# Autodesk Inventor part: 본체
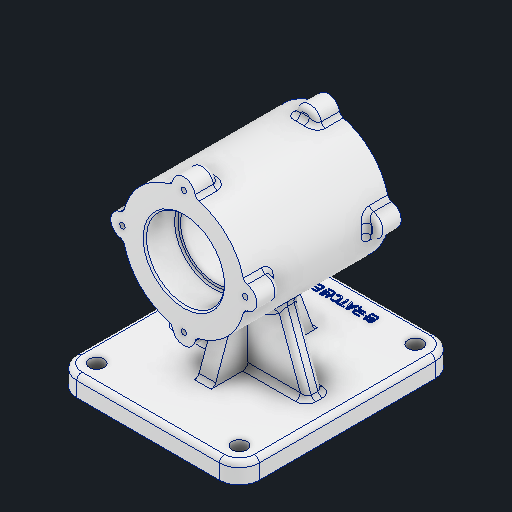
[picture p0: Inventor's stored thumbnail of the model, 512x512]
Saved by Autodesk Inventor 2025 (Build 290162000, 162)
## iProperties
Created: 2025-08
Part Number: 본체
Material: 알루미늄 6061
Document SubType Name: Modeling
Designer: infra08
Density: 2.7 g/cm^3
Appearance: 알루미늄 - 평지
Mass: 1223.04 g
Surface Area: 803.281 cm^2
Volume: 452.979 cm^3
Author: infra08
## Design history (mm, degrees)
sketch "스케치1"
  geometry: L1 (55, 65)-(-55, 65); L2 (-55, 65)-(-55, -65); L3 (-55, -65)-(55, -65); L4 (55, -65)-(55, 65); L5 (55, 65)-(-55, -65); L6 (-55, 65)-(55, -65); C1 r 4.5 at (-43, 53); C2 r 4.5 at (-43, -53); C3 r 4.5 at (43, -53); C4 r 4.5 at (43, 53); 2 further points
  constraints: 12 end point, 4 centre point, 2 horizontal alignment, 2 midpoint, 2 parallel, 2 vertical alignment, 1 coincident, 1 horizontal, 1 perpendicular
  dimensions: "d0" = 130 distance of L1.end L2.end; "d1" = 110 distance of L2.end L3.end; "d3" = 9 diameter of C1; "d4" = 9 diameter of C3; "d5" = 9 diameter of C2; "d6" = 12 distance from line of C1.centre L1; "d7" = 12 distance from line of L3 C2.centre (= d6); "d8" = 12 distance from line of L2 C1.centre (= d6); "d9" = 12 distance from line of L4 C3.centre; "d10" = 9 diameter of C4
extrude "돌출1" new body sketch "스케치1" distance "d11" = 12; taper "d12" = 0 deg
sketch "스케치2"
  geometry: L1 (70, 43.5)-(107, 43.5); L2 (107, -43.5)-(70, -43.5); L3 (70, -43.5)-(70, 43.5); L4 (93.5, 43.5)-(93.5, 24.5); L5 (93.5, 24.5)-(91, 24.5); L6 (91, 24.5)-(91, -24.5); L7 (91, -24.5)-(93.5, -24.5); L8 (93.5, -24.5)-(93.5, -43.5); L9 (107, 43.5)-(107, -43.5); L10 (0, 65)-(0, -65) reference; L11 (-12, -65)-(-12, 65) reference; 2 further points
  constraints: 18 end point, 4 perpendicular, 4 point on line, 2 vertical, 1 horizontal, 1 midpoint
  dimensions: "d13" = 87 distance between parallel lines of L2 L1; "d14" = 19 distance of L4.start L4.end; "d15" = 19 distance of L7.end L8.end (= d14); "d16" = 37 distance between parallel lines of L3 L9; "d17" = 23.5 distance between parallel lines of L3 L4; "d18" = 21 distance between parallel lines of L3 L6; "d19" = 43.5 distance from line of point (0, 0) L1 (= 0.5 x d13); "d20" = 82 distance between parallel lines of L11 L3
revolve "회전1" sketch "스케치2" stored, may be unused: angle "d21" = 90 deg
sketch "스케치3"
  geometry: C1 r 7 at (0, 37); 4 further points
  constraints: 1 centre point, 1 vertical alignment, 2 other
  dimensions: "d22" = 14 diameter of C1
extrude "돌출2" join sketch "스케치3" distance "d23" = 14; taper "d24" = 0 deg
sketch "스케치4"
  geometry: A1 r 7 centre (0, 0) between (6.969, -0.662) and (-6.969, -0.662) reference; 1 further point
hole "구멍1" sketch "스케치4" at (0, 0) diameter "d25" = 3.242; stored, may be unused: countersink angle "d29" = 90 deg, drill point angle "d31" = 118 deg; dims "d26" = 8, "d27" = 4, "d28" = 2, "d30" = 10
sketch "스케치5"
  geometry: L1 (0, -30)-(33, -17.989); L2 (0, -65)-(0, -30); L3 (31.379, 43.5)-(34.621, 43.5) reference; L4 (33, -29.5)-(33, 29.5) reference; L5 (33, 0)-(0, 0); L6 (0, 30)-(33, 17.989); 1 further point
  constraints: 8 end point, 2 midpoint, 2 symmetric about line, 2 vertical alignment, 1 horizontal, 1 vertical
  dimensions: "d36" = 110 deg angle of L2 L1; "d37" = 30 distance of L5.end L1.start
sketch "스케치7"
  geometry: L1 (55, 0)-(-55, 0) reference; L2 (-41, 0)-(-25.336, 43.036); L3 (-25.336, 43.036)-(-25.336, 0); L4 (-55, 0)-(55, 0) reference; L5 (0, 26)-(0, 0); A1 r 37 centre (0, 70) between (-36.338, 63.031) and (-6.969, 33.662) reference; A2 r 7 centre (0, 33) between (-6.969, 33.662) and (6.969, 33.662) reference
  constraints: 6 end point, 2 point on circle, 2 point on line, 1 perpendicular, 1 vertical
  dimensions: "d47" = 14 distance of L1.end L2.start; "d48" = 110 deg angle of L1 L2
sketch "스케치6"
  geometry: L1 (-5, 17.989)-(5, 17.989); L2 (5, 17.989)-(5, -17.989); L3 (5, -17.989)-(-5, -17.989); L4 (-5, -17.989)-(-5, 17.989); L5 (-5, 17.989)-(5, -17.989); L6 (5, 17.989)-(-5, -17.989); L7 (-25.336, 5)-(25.336, 5); L8 (25.336, 5)-(25.336, -5); L9 (25.336, -5)-(-25.336, -5); L10 (-25.336, -5)-(-25.336, 5); L11 (-25.336, 5)-(25.336, -5); L12 (25.336, 5)-(-25.336, -5); L13 (0, 30)-(0, 17.989) reference; L14 (-41, 0)-(-25.336, 0) reference; L15 (-25.336, 0)-(25.336, 0); L16 (25.336, 0)-(25.336, -10); L17 (25.336, -10)-(-25.336, -10); L18 (-25.336, -10)-(-25.336, 0); L19 (-25.336, 0)-(25.336, -10); L20 (25.336, 0)-(-25.336, -10); L21 (-55, 65)-(55, 65) reference; L22 (5, 11.484)-(-5, 11.484); L23 (-5, 11.484)-(-5, -21.484); L24 (-5, -21.484)-(5, -21.484); L25 (5, -21.484)-(5, 11.484); L26 (5, 11.484)-(-5, -21.484); L27 (-5, 11.484)-(5, -21.484); 16 further points
  constraints: 48 end point, 13 midpoint, 8 parallel, 4 coincident, 4 horizontal, 4 perpendicular, 2 vertical alignment
  dimensions: "d38" = 10 distance between parallel lines of L4 L2; "d49" = 10 distance between parallel lines of L7 L9; "d66" = 70 distance from line of point (0, -5) L21; "d67" = 10 distance of L17.end L15.start; "d79" = 10 distance of L23.end L24.end
extrude "돌출3" join sketch "스케치6" stored distance "d39" = 14; taper "d40" = 0 deg
feature "리브1" dims "d41" = 1, "d42" = 10, "d43" = 0, "d44" = 0, "d45" = 1, "d46" = 1
feature "리브3" dims "d56" = 1, "d57" = 10, "d58" = 0, "d59" = 0, "d60" = 1, "d61" = 1
feature "리브4" dims "d68" = 1, "d69" = 10, "d70" = 0, "d71" = 0, "d72" = 1, "d73" = 1
fillet "모깎기1" dims "d62" = 12
fillet "모깎기3" dims "d64" = 3
sketch "스케치8" dims "d0" = 130, "d1" = 110, "d3" = 9, "d4" = 9, "d5" = 9, "d6" = 12, "d7" = 12 (= d6), "d8" = 12 (= d6), "d9" = 12, "d10" = 9
  geometry: L1 (21.187, 50.113)-(-21.187, 50.113); L2 (-21.187, 50.113)-(-21.187, 55.887); L3 (-21.187, 55.887)-(21.187, 55.887); L4 (21.187, 55.887)-(21.187, 50.113); L5 (41, 0)-(41, -10) reference; 4 further points
  constraints: 3 midpoint, 1 vertical alignment, 2 other
  dimensions: "d74" = 58 vertical distance of point (21.187, 53) point (41, -5)
feature "엠보싱1" sketch "스케치8" dims "d0" = 130, "d1" = 110, "d3" = 9, "d4" = 9, "d5" = 9, "d6" = 12, "d7" = 12 (= d6), "d8" = 12 (= d6), "d9" = 12, "d10" = 9, "d13" = 87, "d14" = 19, "d15" = 19 (= d14), "d16" = 37, "d17" = 23.5, "d18" = 21, "d19" = 43.5 (= 0.5 x d13), "d20" = 82, "d75" = 0.5, "d76" = 0
fillet "모깎기4" dims "d77" = 3
fillet "모깎기6" dims "d80" = 1
chamfer "모따기1" distance "d81" = 1; stored, may be unused: second distance "d82" = 2, angle "d83" = 45 deg
node "솔리드1"
pattern_circular "원형 패턴1" dims "d33" = 360 deg
mirror "미러1"
mirror "미러3"
feature "A9D066F2-1C7D-4E18-AEED-F7BC21143FA4" dims "d25" = 3.242, "d26" = 8, "d27" = 4, "d28" = 2, "d29" = 90 deg, "d30" = 10, "d31" = 118 deg
